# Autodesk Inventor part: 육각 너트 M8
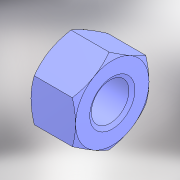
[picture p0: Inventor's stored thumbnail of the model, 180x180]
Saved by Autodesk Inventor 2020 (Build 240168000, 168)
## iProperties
Created: 2024-11
Part Number: 육각 너트 M8
Material: 강철, 연강
Description: 6각 너트 및 6각 가는 너트
Document SubType Name: Modeling
Designer: 1강의실14
Density: 7.85 g/cm^3
Appearance: 기본값
Author: jhkim
Sending System: Autodesk Inventor 2025
Preprocessor: ST-DEVELOPER v20
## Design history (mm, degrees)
feature "Solid1"
node "솔리드1"
